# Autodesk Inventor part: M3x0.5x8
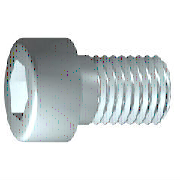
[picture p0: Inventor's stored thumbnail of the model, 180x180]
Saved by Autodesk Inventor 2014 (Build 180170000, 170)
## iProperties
IsCustomPart: 1
Company: 한국ATC센터
Created: 2009-02
Part Number: M3x0.5x8
Material: 강, 연강
Description: 6각머리 태핑 나사
Document SubType Name: Modeling
Standard: KS B 1003
Designer: KYOUNG IL JANG
Standards Organization: KS
Language: ko-KR
Size Designation: M 4 x 12
Categories: <MemberInstance><Categories><Category DisplayName="조임쇠" InternalName="e4da775c-781d-43d5-af7c-5136215cf5a6" Mnemonic="FSTN"><Category DisplayName="볼트" InternalN
Density: 7.86 g/cm^3
Mass: 1.37432 g
Surface Area: 2.58399 cm^2
Volume: 0.174849 cm^3
Vendor: CBT Solutions
Appearance: 강철
Author: KYOUNG IL JANG
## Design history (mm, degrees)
sketch "스케치1"
  geometry: L1 (-0.867, 0)-(16, 0); L2 (16, 0)-(16, 1.5); L3 (16, 1.5)-(1.25, 1.5); L4 (1.25, 1.5)-(0.943, 1.5); L5 (0.943, 1.5)-(0, 1.5); L6 (0, 1.5)-(0, 2.75); L7 (0, 2.75)-(-3, 2.75); L8 (-3, 2.75)-(-3, 1.443); L9 (-3, 1.443)-(-1.7, 1.443); L10 (-1.7, 1.443)-(-0.867, 0); L11 (-6.8, 0)-(19.8, 0) reference; L12 (0, -0.55)-(0, 3.3) reference; L13 (1.25, 1.5)-(0, 1.5)
  constraints: 22 end point, 6 parallel, 2 collinear, 2 perpendicular, 1 horizontal, 1 point on line
  dimensions: "d1" = 14.75 distance from line of L3.end L2 (= GEL); "d2" = 0.30683 distance of L4.end L3.end (computed from GAL); "d3" = 3 distance between parallel lines of L8 L6 (= KOH); "d4" = 1.3 distance of L8.end L9.end (= INTI); "d5" = 60 deg angle of L10 L1; "d6" = 3 diameter of L3 L1 (= GD); "d7" = 3 diameter of L5 L1 (= BDM); "d8" = 2.88675 diameter of L9 L1 (= 1.1547 x SW); "d9" = 5.5 diameter of L7 L1 (= KOD); "d26" = 16 distance between parallel lines of L12 L2 (= NLG)
revolve "본체" sketch "스케치1" stored, may be unused: angle "d10" = 90 deg
sketch "스케치2"
  geometry: L1 (0, -3.85)-(0, 3.85) reference; L2 (-3.85, 0)-(3.85, 0) reference; L3 (1.443, 0)-(0.722, -1.25); L4 (0.722, -1.25)-(-0.722, -1.25); L5 (-0.722, -1.25)-(-1.443, 0); L6 (-1.443, 0)-(-0.722, 1.25); L7 (-0.722, 1.25)-(0.722, 1.25); L8 (0.722, 1.25)-(1.443, 0); 2 further points
  constraints: 12 end point, 1 coincident, 1 horizontal alignment, 1 point on line, 12 other
extrude "슬롯" join sketch "스케치2" stored distance "d11" = 10; taper "d12" = 0 deg
workplane "Work Plane1"
fillet "Fillet2" dims "d30" = 0.1 (= R)
body "Solid1"
fillet "모깎기1" dims "d17" = 0.3 (= RR)
feature "스레드" dims "d13" = 14.75 (= GEL), "d14" = 0
chamfer "모따기1" distance "d15" = 0.30673 (= -0.5 x SPD + 0.5 x GD); stored, may be unused: second distance "d16" = 0.30673 (= GUL), angle "d27" = 45 deg
other parameters: "GD" = 3 (= NND) [user parameter; used in 2 equation terms], "NLG" = 16 [user parameter; used in 1 equation term], "GEL" = 14.75 [user parameter; used in 2 equation terms], "KOD" = 5.5 [user parameter; used in 1 equation term], "KOH" = 3 [user parameter; used in 1 equation term], "INTI" = 1.3 [user parameter; used in 1 equation term], "GAL" = 0.30673 (= 0.61345 x PTC) [user parameter; used in 1 equation term], "GUL" = 0.30673 (= 0.61345 x PTC) [user parameter; used in 1 equation term], "BDM" = 3 (= NND) [user parameter; used in 1 equation term], "SW" = 2.5 [user parameter; used in 2 equation terms], "RR" = 0.3 [user parameter; used in 1 equation term], "SPD" = 2.38655 (= NND - 1.2269 x PTC) [user parameter; used in 1 equation term], "d19" = 0, "d28" = 0, "d29" = 0, "R" = 0.1 [user parameter; used in 1 equation term], "PHH" = 0.1 [user parameter], "GD1" = 2.38655 (= THREADDIA - 1.2269 x PTC) [user parameter], "THREADDIA" = 3 [user parameter; used in 1 equation term], "FAWI" = 45 deg [user parameter], "PTC" = 0.5 [user parameter; used in 5 equation terms], "NND" = 3 [user parameter; used in 3 equation terms], "TOA" = 30 deg [user parameter], "E0" = 2.8875 (= 1.155 x SW) [user parameter]
